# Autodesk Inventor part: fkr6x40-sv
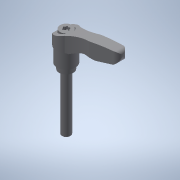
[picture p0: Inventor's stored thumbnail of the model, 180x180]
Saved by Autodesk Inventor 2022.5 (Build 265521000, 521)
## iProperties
Created: 2017-09
Part Number: fkr6x40-sv
Material: 一般
Document SubType Name: Modeling
Designer: imaocorp
Density: 1 g/cm^3
Appearance: 既定
Author: imaocorp
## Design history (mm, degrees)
node "fkr6x40-sv.x_t1"
node "fkr6x40-sv"
node "Base1"
